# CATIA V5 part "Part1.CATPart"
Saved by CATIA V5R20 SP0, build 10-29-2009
Part number: Part1
Bounding box of the stored display mesh (mm): x -10 to 10, y 10 to 30, z -10 to 10
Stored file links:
  E:\Ehsan\My Websites\CATIA98.ir\3. Tutorials\3. Assembely Design\Assembly Design-17\Part1.CATPart
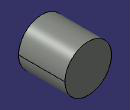
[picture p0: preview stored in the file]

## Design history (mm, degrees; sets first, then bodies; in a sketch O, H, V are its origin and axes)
Body1 (main body)
  DatumSurface1
  DatumCurve1
  DatumCurve2
  Sketch1 on face of DatumSurface1, origin (0, 10, 0), H (-1, 0, 0), V (0, 0, 1)
    projected circle E1 centre (0, 0) radius 10 from edge of DatumCurve2
  Pad1: profile Sketch1, direction (0, 1, 0), length 20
